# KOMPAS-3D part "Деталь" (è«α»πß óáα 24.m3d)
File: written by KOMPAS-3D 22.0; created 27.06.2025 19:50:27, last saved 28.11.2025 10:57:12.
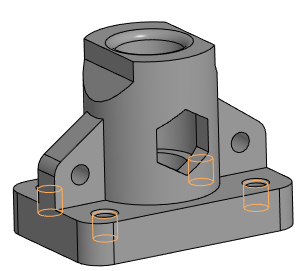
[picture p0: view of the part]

Document properties: Автор: alymovy@yandex.ru; Организация: HP; Полное имя файла: Корпус вар 24.cdw

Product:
- Part/product: Деталь
    Материал: Полипропилен ГОСТ 26996-86 (density 900 kg/m3)
    Масса: 0.466119
    Форматы листов документа: A3

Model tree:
1. Эскиз:1
2. Элемент выдавливания:1
     Расстояние 1 = 25
3. Скругление:1  (with: Элемент выдавливания:1)
     Радиус = 15
4. Эскиз:2  (with: Элемент выдавливания:1)
5. Элемент выдавливания:2
     Расстояние 1 = 85
6. Эскиз:3  (with: Скругление:1, Элемент выдавливания:2)
7. Ребро жесткости:1
     Толщина стенки 1 = 18; Толщина стенки 2 = 1
8. Зеркальный массив:1
9. Экземпляр ( 1 )
10. Экземпляр ( 2 )  (with: Ребро жесткости:1)
11. Эскиз:4  (with: Элемент выдавливания:2)
12. Элемент вращения:1
     Угол 1 = 360
13. Эскиз:5
14. Элемент выдавливания:3
     Расстояние 1 = 47.5
15. Скругление:2  (with: Элемент вращения:1)
     Радиус = 5
16. Эскиз:6  (with: Ребро жесткости:1)
17. Элемент выдавливания:4
18. Эскиз:7  (with: Элемент выдавливания:1, Элемент выдавливания:2)
19. Скругление:3  (with: Элемент вращения:1)
     Радиус = 5
20. Эскиз:8  (with: Элемент выдавливания:2)
21. Элемент выдавливания:5
     Расстояние 1 = 47.5
22. Отверстие:2  (with: Элемент выдавливания:1, Ребро жесткости:1)  (labels: M14)
     Глубина выреза = 20; Диаметр отверстия = 11.8349; Угол конуса дна = 118; Расстояние 1 = -21; Расстояние 2 = 20; Диаметр зенковки = 15.8349; Глубина зенковки = 2; Угол зенковки = 90
23. M14  (labels: cil0_24705-2004 coarse)
     Длина резьбы = 15; Шаг резьбы = 2; Номинальный диаметр резьбы = 14
24. Зеркальный массив:4  (with: Экземпляр ( 1 ), Экземпляр ( 2 ), Отверстие:2)
25. Зеркальный массив:5  (with: Экземпляр ( 1 ), Экземпляр ( 2 ), Зеркальный массив:4, Отверстие:2)
26. Экземпляр ( 2 )  (with: Отверстие:2)

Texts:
  Загружение0
  Точка начала. Х
  Точка начала. Y
  Точка начала. Z
  Линейный размер с обрывом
